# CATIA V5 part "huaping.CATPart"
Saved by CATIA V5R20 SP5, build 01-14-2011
Part number: 花瓶
Bounding box of the stored display mesh (mm): x -27.47 to 27.47, y -27.47 to 27.443, z 0 to 120
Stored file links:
  E:\180522212\huaping.CATPart
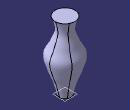
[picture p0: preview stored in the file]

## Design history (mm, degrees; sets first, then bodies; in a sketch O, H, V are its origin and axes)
Body1 (main body)
  Plane1: type Offset, RefPlane xy-plane, Offset 20
  Plane2: type Offset, RefPlane Plane1, Offset 20
  Plane3: type Offset, RefPlane Plane2, Offset 20
  Plane4: type Offset, RefPlane Plane3, Offset 20
  Plane5: type Offset, RefPlane Plane4, Offset 20
  Plane6: type Offset, RefPlane Plane5, Offset 20
  Sketch1 on xy-plane, origin (0, 0, 0), H (1, 0, 0), V (0, 1, 0)
    circle A1 centre (0, 0) radius 10
    point P1 (10, 0)
    radius A1 = 10
    coincidence: A1 P1, P1 H
  Sketch2 on Plane1, origin (0, 0, 20), H (1, 0, 0), V (0, 1, 0)
    circle A1 centre (0, 0) radius 15
    point P1 (15, 0)
    radius A1 = 15
    coincidence: A1 P1, P1 H
  Sketch3 on Plane2, origin (0, 0, 40), H (1, 0, 0), V (0, 1, 0)
    circle A1 centre (0, 0) radius 22.5
    point P1 (22.5, 0)
    radius A1 = 22.5
    coincidence: A1 P1, P1 H
  Sketch4 on Plane3, origin (0, 0, 60), H (1, 0, 0), V (0, 1, 0)
    circle A1 centre (0, 0) radius 27.5
    point P1 (27.5, 0)
    radius A1 = 27.5
    coincidence: A1 P1, P1 H
  Sketch5 on Plane4, origin (0, 0, 80), H (1, 0, 0), V (0, 1, 0)
    circle A1 centre (0, 0) radius 19
    point P1 (19, 0)
    radius A1 = 19
    coincidence: A1 P1, P1 H
  Sketch6 on Plane5, origin (0, 0, 100), H (1, 0, 0), V (0, 1, 0)
    circle A1 centre (0, 0) radius 12.5
    point P1 (12.5, 0)
    radius A1 = 12.5
    coincidence: A1 P1, P1 H
  Sketch7 on Plane6, origin (0, 0, 120), H (1, 0, 0), V (0, 1, 0)
    circle A1 centre (0, 0) radius 17.5
    point P1 (17.5, 0)
    radius A1 = 17.5
    coincidence: A1 P1, P1 H
  Loft1: solid, Sections (Sketch1; Sketch2; Sketch3; Sketch4; Sketch5; Sketch6; Sketch7)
